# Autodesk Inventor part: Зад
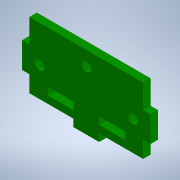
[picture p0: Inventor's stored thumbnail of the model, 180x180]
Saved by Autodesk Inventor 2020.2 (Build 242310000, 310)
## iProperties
Created: 2020-04
Part Number: Зад
Material: Типовые
Document SubType Name: Modeling
Designer: Алексей
Density: 1 g/cm^3
Appearance: По умолчанию
Author: Алексей
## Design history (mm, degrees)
sketch "Эскиз1"
  geometry: L1 (-10, -11)-(-14, -11) reference; L2 (52, -11)-(52, 3) reference; L3 (56, -11)-(52, -11) reference; L4 (56, 3)-(56, -11) reference; L5 (56, 3)-(52, 3) reference; L6 (-14, 16)-(-10, 16) reference; L7 (52, -20)-(28, -20) reference; L8 (52, 16)-(56, 16) reference; L9 (-10, 16)-(52, 16); L10 (52, 16)-(52, -20); L11 (52, -20)-(-10, -20); L12 (-10, -20)-(-10, 16); L13 (14, -20)-(28, -20) reference; L14 (14, -24)-(14, -20) reference; L15 (28, -24)-(14, -24) reference; L16 (28, -24)-(28, -20) reference; L17 (-14, 3)-(-10, 3); L18 (-14, 3)-(-10, 3) reference; L19 (-10, 16)-(-10, 3) reference; L20 (-14, 16)-(-10, 16) reference; L21 (-14, 16)-(-14, 3) reference; L22 (52, 3)-(56, 3) reference; L23 (56, 16)-(56, 3) reference; L24 (52, 16)-(56, 16) reference; L25 (52, 16)-(52, 3) reference; L26 (56, -11)-(52, -11) reference; L27 (52, -11)-(52, -24) reference; L28 (52, -24)-(56, -24) reference; L29 (56, -11)-(56, -24) reference; L30 (-10, -11)-(-14, -11) reference; L31 (-14, -11)-(-14, -24) reference; L32 (-14, -24)-(-10, -24) reference; L33 (-10, -11)-(-10, -24) reference; 9 further points; 1 other entity
  constraints: 10 end point, 2 parallel, 2 perpendicular, 1 horizontal, 1 point on line, 1 vertical alignment, 1 other
extrude "Выдавливание1" new body sketch "Эскиз1" distance "d0" = 4; taper "d1" = 0 deg
sketch "Эскиз2"
  geometry: L1 (14, -16)-(14, -12) reference; L2 (0, -16)-(14, -16) reference; L3 (0, -12)-(14, -12) reference; L4 (0, -16)-(0, -12) reference; L5 (28, -16)-(42, -16) reference; L6 (42, -16)-(42, -12) reference; L7 (28, -12)-(42, -12) reference; L8 (28, -16)-(28, -12) reference; 1 further point
extrude "Выдавливание2" cut sketch "Эскиз2" extent not by distance; stored distance "d2" = 0; taper "d3" = 0 deg
sketch "Эскиз3"
  geometry: L1 (-14, 3)-(-14, -11) reference; L2 (56, -11)-(56, 3) reference; L3 (52, 3)-(52, 16) reference; L4 (-10, 16)-(-10, 3) reference; C1 r 2.5 at (-4.5, -4); C2 r 2.5 at (46.5, -4); 2 further points
  constraints: 2 centre point, 2 horizontal alignment, 2 midpoint
  dimensions: "d4" = 5 diameter of C1; "d5" = 5 diameter of C2; "d7" = 5.5 distance from line of L3 C2.centre; "d10" = 5.5 distance from line of L4 C1.centre
extrude "Выдавливание3" cut sketch "Эскиз3" extent not by distance; stored distance "d8" = 0; taper "d9" = 0 deg
sketch "Эскиз4"
  geometry: L1 (52, 16)-(-10, 16) reference; C1 r 2.5 at (21, 8); 2 further points
  constraints: 1 centre point, 1 midpoint, 1 vertical alignment
  dimensions: "d11" = 5 diameter of C1; "d12" = 8 distance from line of L1 C1.centre
extrude "Выдавливание4" cut sketch "Эскиз4" extent not by distance; stored distance "d13" = 0; taper "d14" = 0 deg
node "Твердое тело1"
node "Ссылка2"
node "Ссылка3"
node "Ссылка4"
node "Ссылка5"
node "Ссылка6"
node "Ссылка7"
node "Ссылка8"
node "Ссылка9"
node "Ссылка10"
node "Ссылка11"
node "Ссылка12"
node "Ссылка13"
node "Ссылка14"
node "Ссылка15"
node "Ссылка16"
node "Ссылка17"
node "Ссылка18"
feature "Машинка.iam"
